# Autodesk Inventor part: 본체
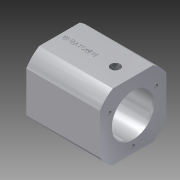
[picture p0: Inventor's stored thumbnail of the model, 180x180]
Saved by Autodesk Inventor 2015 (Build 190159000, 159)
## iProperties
Created: 2020-02
Part Number: 본체
Material: 알루미늄 6061
Document SubType Name: Modeling
Designer: LINEART-SSD.D4.16.05
Density: 2.7 g/cm^3
Appearance: 알루미늄 - 평지
Mass: 537.891 g
Surface Area: 342.742 cm^2
Volume: 199.219 cm^3
Author: LINEART-SSD.D4.16.05
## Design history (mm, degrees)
sketch "스케치1"
  geometry: L1 (0, 0)-(83, 0); L2 (0, 0)-(0, 14); L3 (0, 14)-(12, 14); L4 (12, 14)-(12, 32); L5 (12, 32)-(83, 32); L6 (83, 32)-(83, 0)
  constraints: 12 end point, 4 perpendicular, 1 horizontal, 1 vertical
  dimensions: "d0" = 83 distance of L1.start L1.end; "d1" = 28 diameter of L3 L1; "d2" = 64 diameter of L5 L1; "d3" = 12 distance from line of L3.end L2
revolve "회전1" sketch "스케치1" stored, may be unused: angle "d4" = 90 deg
sketch "스케치2"
  geometry: 1 further point
hole "구멍1" sketch "스케치2" at (0, 0) diameter "d5" = 8.917; stored, may be unused: countersink angle "d9" = 90 deg, drill point angle "d11" = 118 deg; dims "d6" = 14, "d7" = 4, "d8" = 2, "d10" = 17
sketch "스케치3"
  geometry: L1 (0, 0)-(83, 0); L2 (83, 0)-(83, 20); L3 (83, 20)-(21, 20); L4 (21, 20)-(21, 0); L5 (19.679, 0)-(17, 4.458) reference; L6 (17, 4.458)-(0, 4.458) reference; L7 (0, 4.458)-(0, 14) reference; L8 (0, 14)-(12, 14) reference; L9 (12, 14)-(12, 32) reference; L10 (12, 32)-(83, 32) reference; L11 (83, 32)-(83, -32) reference; L12 (83, -32)-(12, -32) reference; L13 (12, -32)-(12, -14) reference; L14 (12, -14)-(0, -14) reference; L15 (0, -14)-(0, -4.458) reference; L16 (0, -4.458)-(17, -4.458) reference; L17 (17, -4.458)-(19.679, 0) reference
  constraints: 8 end point, 2 perpendicular, 1 collinear, 1 horizontal, 1 point on line, 1 vertical
  dimensions: "d12" = 40 diameter of L3 L1; "d13" = 62 distance between parallel lines of L4 L2
revolve "회전2" sketch "스케치3" stored, may be unused: angle "d14" = 90 deg
sketch "스케치4"
  geometry: C1 r 4.458 at (0, 0) reference; C2 r 14 at (0, 0) reference; C3 r 2 at (0, 0); 1 further point
  constraints: 1 centre point, 1 coincident
  dimensions: "d15" = 4 diameter of C3
extrude "돌출1" cut sketch "스케치4" distance "d16" = 45.5; taper "d17" = 0 deg
sketch "스케치5"
  geometry: L1 (-32, 32)-(32, 32); L2 (32, 32)-(32, -32); L3 (32, -32)-(-32, -32); L4 (-32, -32)-(-32, 32); L5 (-32, 32)-(32, -32); L6 (32, 32)-(-32, -32); C1 r 4.458 at (0, 0) reference; C2 r 14 at (0, 0) reference; C3 r 32 at (0, 0) reference; 1 further point
  constraints: 12 end point, 2 midpoint, 2 parallel, 1 horizontal, 1 perpendicular
  dimensions: "d18" = 64 distance of L2.end L3.end; "d19" = 64 distance of L1.end L2.end
extrude "돌출2" join sketch "스케치5" distance "d20" = 71; taper "d21" = 0 deg
sketch "스케치6"
  geometry: L1 (0, 0)-(0, 64) reference; L2 (0, 64)-(64, 64) reference; L3 (64, 64)-(64, 0) reference; L4 (64, 0)-(0, 0) reference; L5 (12.449, 64)-(51.551, 64); L6 (12.449, 0)-(51.551, 0); L7 (0, 51.551)-(0, 12.449); L8 (64, 51.551)-(64, 12.449); C1 r 4.458 at (32, 32) reference; C2 r 14 at (32, 32) reference; A1 r 37.5 centre (32, 32) between (12.449, 64) and (0, 51.551); A2 r 37.5 centre (32, 32) between (0, 12.449) and (12.449, 0); A3 r 37.5 centre (32, 32) between (51.551, 0) and (64, 12.449); A4 r 37.5 centre (32, 32) between (64, 51.551) and (51.551, 64); 1 further point
  constraints: 8 end point, 8 point on circle, 8 point on line, 4 centre point, 3 collinear, 3 concentric, 1 coincident
  dimensions: "d24" = 37.5 radius of A4
extrude "돌출3" cut sketch "스케치6" distance "d25" = 71; taper "d26" = 0 deg
sketch "스케치7" dims "d27" = 52
  geometry: L1 (51.551, -12.449)-(12.449, -12.449) reference; L2 (0, 0)-(0, 39.102) reference; L3 (12.449, 51.551)-(51.551, 51.551) reference; L4 (64, 39.102)-(64, 0) reference; C1 r 4.458 at (32, 19.551) reference; C2 r 14 at (32, 19.551) reference; A1 r 37.5 centre (32, 19.551) between (51.551, -12.449) and (64, 0) reference; A2 r 37.5 centre (32, 19.551) between (0, 0) and (12.449, -12.449) reference; A3 r 37.5 centre (32, 19.551) between (12.449, 51.551) and (0, 39.102) reference; A4 r 37.5 centre (32, 19.551) between (64, 39.102) and (51.551, 51.551) reference; 3 further points
  constraints: 2 vertical alignment, 1 coincident, 2 other
hole "구멍2" sketch "스케치7" at (32, 45.551) diameter "d28" = 3.242; stored, may be unused: countersink angle "d32" = 90 deg, drill point angle "d34" = 118 deg; dims "d29" = 10, "d30" = 4, "d31" = 2, "d33" = 12
sketch "스케치8" dims "d38" = 52
  geometry: L1 (0, 0)-(0, 39.102) reference; L2 (12.449, 51.551)-(51.551, 51.551) reference; L3 (64, 39.102)-(64, 0) reference; L4 (51.551, -12.449)-(12.449, -12.449) reference; C1 r 20 at (32, 19.551) reference; A1 r 37.5 centre (32, 19.551) between (0, 0) and (12.449, -12.449) reference; A2 r 37.5 centre (32, 19.551) between (12.449, 51.551) and (0, 39.102) reference; A3 r 37.5 centre (32, 19.551) between (64, 39.102) and (51.551, 51.551) reference; A4 r 37.5 centre (32, 19.551) between (51.551, -12.449) and (64, 0) reference; 3 further points
  constraints: 2 vertical alignment, 1 coincident, 2 other
hole "구멍3" sketch "스케치8" at (32, 45.551) diameter "d39" = 3.242; stored, may be unused: countersink angle "d43" = 90 deg, drill point angle "d45" = 118 deg; dims "d40" = 10, "d41" = 4, "d42" = 2, "d44" = 12
sketch "스케치9"
  geometry: L1 (71, 39.551)-(71, -0.449) reference; 2 further points
  constraints: 1 horizontal alignment
  dimensions: "d49" = 17 distance from line of point (54, 19.551) L1
hole "구멍4" sketch "스케치9" at (54, 19.551) diameter "d50" = 8.917; stored, may be unused: countersink angle "d54" = 90 deg, drill point angle "d56" = 118 deg; dims "d51" = 6, "d52" = 4, "d53" = 2, "d55" = 9
sketch "스케치10"
  geometry: L1 (0, 39.102)-(71, 39.102) reference; L2 (71, 39.102)-(71, 0) reference; L3 (71, 0)-(0, 0) reference; L4 (0, 0)-(0, 39.102) reference; C1 r 4.458 at (54, 19.551) reference; C2 r 2 at (54, 19.551); 1 further point
  constraints: 1 centre point, 1 coincident
  dimensions: "d57" = 4 diameter of C2
extrude "돌출4" cut sketch "스케치10" distance "d58" = 28.25; taper "d59" = 0 deg
sketch "스케치11"
  geometry: L1 (0, 5.551)-(0, 33.551) reference; 2 further points
  constraints: 1 horizontal alignment, 1 other
  dimensions: "d60" = 20 distance from line of point (20, 19.551) L1
feature "엠보싱1" sketch "스케치11" dims "d14" = 90 deg, "d61" = 0.5, "d62" = 0
chamfer "모따기2" distance "d66" = 1; stored, may be unused: second distance "d67" = 2, angle "d68" = 45 deg
chamfer "모따기3" distance "d69" = 1.8; stored, may be unused: second distance "d70" = 2, angle "d71" = 15 deg
node "솔리드1"
pattern_circular "원형 패턴1" dims angle "d36" = 360 deg
pattern_circular "원형 패턴2" dims angle "d47" = 360 deg
node "절단 모서리 투영1"
node "절단 모서리 투영2"
node "절단 모서리 투영3"
node "절단 모서리 투영4"
node "절단 모서리 투영5"
node "절단 모서리 투영6"
node "절단 모서리 투영7"
other parameters: "d22" = 75
